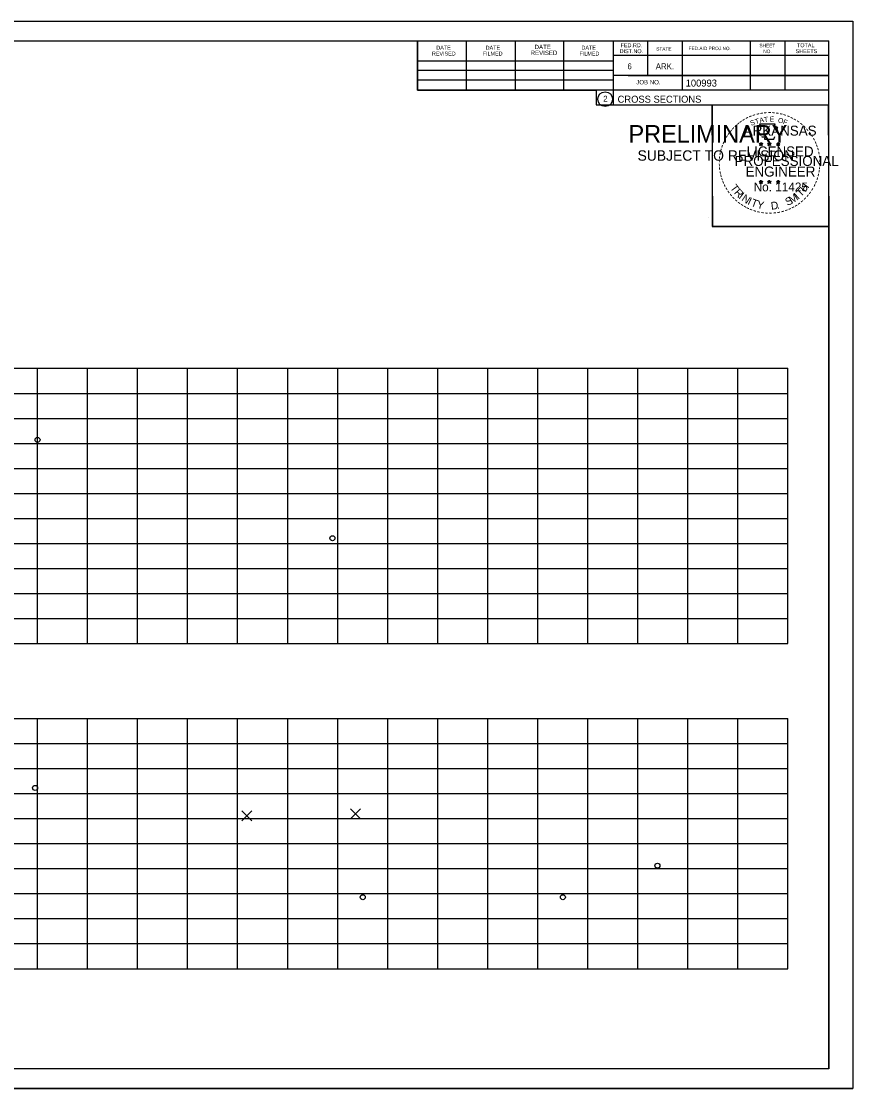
# Model space of a CAD drawing. Extents: x 4667 to 1632277, y -2100 to 724501.
# Drawn here: x 6136.3 to 6302.5, y -1323.8 to -1110.4 of the extents above; entities that cross this region are included whole.
import ezdxf

# ---------------------------------------------------------------- set-up
doc = ezdxf.new("R2010")
doc.units = 0
doc.layers.add('R_Grid', color=7, linetype='Continuous')
doc.layers.add('R_No Plot', color=7, linetype='Continuous')

msp = doc.modelspace()

# ---------------------------------------------------------------- linework, layer by layer
at = {"layer": 'R_Grid'}
for p, q in [((5989.52, -1179.77), (6289.52, -1179.77)), ((6139.52, -1234.77), (6139.52, -1179.77)), ((6149.52, -1234.77), (6149.52, -1179.77)), ((6159.52, -1234.77), (6159.52, -1179.77)), ((6169.52, -1234.77), (6169.52, -1179.77)), ((6179.52, -1234.77), (6179.52, -1179.77)), ((6189.52, -1234.77), (6189.52, -1179.77)), ((6199.52, -1234.77), (6199.52, -1179.77)), ((6209.52, -1234.77), (6209.52, -1179.77)), ((6219.52, -1234.77), (6219.52, -1179.77)), ((6229.52, -1234.77), (6229.52, -1179.77)), ((6239.52, -1234.77), (6239.52, -1179.77)), ((6249.52, -1234.77), (6249.52, -1179.77)), ((6259.52, -1234.77), (6259.52, -1179.77)), ((6269.52, -1234.77), (6269.52, -1179.77)), ((6279.52, -1234.77), (6279.52, -1179.77)), ((6289.52, -1234.77), (6289.52, -1179.77)), ((5989.52, -1184.77), (6289.52, -1184.77)), ((5989.52, -1189.77), (6289.52, -1189.77)), ((5989.52, -1194.77), (6289.52, -1194.77)), ((5989.52, -1199.77), (6289.52, -1199.77)), ((5989.52, -1204.77), (6289.52, -1204.77)), ((5989.52, -1209.77), (6289.52, -1209.77)), ((5989.52, -1214.77), (6289.52, -1214.77)), ((5989.52, -1219.77), (6289.52, -1219.77)), ((5989.52, -1224.77), (6289.52, -1224.77)), ((5989.52, -1229.77), (6289.52, -1229.77)), ((5989.52, -1234.77), (6289.52, -1234.77)), ((5989.52, -1249.77), (6289.52, -1249.77)), ((6139.52, -1299.77), (6139.52, -1249.77)), ((6149.52, -1299.77), (6149.52, -1249.77)), ((6159.52, -1299.77), (6159.52, -1249.77)), ((6169.52, -1299.77), (6169.52, -1249.77)), ((6179.52, -1299.77), (6179.52, -1249.77)), ((6189.52, -1299.77), (6189.52, -1249.77)), ((6199.52, -1299.77), (6199.52, -1249.77)), ((6209.52, -1299.77), (6209.52, -1249.77)), ((6219.52, -1299.77), (6219.52, -1249.77)), ((6229.52, -1299.77), (6229.52, -1249.77)), ((6239.52, -1299.77), (6239.52, -1249.77)), ((6249.52, -1299.77), (6249.52, -1249.77)), ((6259.52, -1299.77), (6259.52, -1249.77)), ((6269.52, -1299.77), (6269.52, -1249.77)), ((6279.52, -1299.77), (6279.52, -1249.77)), ((6289.52, -1299.77), (6289.52, -1249.77)), ((5989.52, -1254.77), (6289.52, -1254.77)), ((5989.52, -1259.77), (6289.52, -1259.77)), ((5989.52, -1264.77), (6289.52, -1264.77)), ((5989.52, -1269.77), (6289.52, -1269.77)), ((5989.52, -1274.77), (6289.52, -1274.77)), ((5989.52, -1279.77), (6289.52, -1279.77)), ((5989.52, -1284.77), (6289.52, -1284.77)), ((5989.52, -1289.77), (6289.52, -1289.77)), ((5989.52, -1294.77), (6289.52, -1294.77)), ((5989.52, -1299.77), (6289.52, -1299.77))]:
    msp.add_line(p, q, dxfattribs=at)
at = {"layer": 'R_No Plot'}
for p, q in [((5969.12, -1110.41), (6302.46, -1110.41)), ((5981.52, -1114.31), (6297.7, -1114.31)), ((6215.44, -1124.19), (6215.44, -1114.31)), ((6225.3, -1124.19), (6225.3, -1114.51)), ((6235.06, -1124.19), (6235.06, -1114.51)), ((6244.74, -1124.19), (6244.74, -1114.51)), ((6254.6, -1114.31), (6254.6, -1127.11)), ((6261.44, -1114.31), (6261.44, -1121.25)), ((6268.38, -1114.31), (6268.38, -1124.19)), ((6281.96, -1114.31), (6281.96, -1124.19)), ((6288.9, -1114.31), (6288.9, -1124.19)), ((6297.7, -1319.77), (6297.7, -1114.31)), ((6297.7, -1117.25), (6254.6, -1117.25)), ((6297.7, -1117.23), (6297.7, -1117.23)), ((6215.44, -1118.33), (6254.6, -1118.33)), ((6215.44, -1120.19), (6254.6, -1120.19)), ((6215.44, -1124.19), (6215.44, -1122.13)), ((6215.44, -1122.13), (6254.6, -1122.13)), ((6297.7, -1121.25), (6254.6, -1121.25)), ((6257.56, -1121.25), (6297.7, -1121.25)), ((6297.7, -1124.19), (6215.44, -1124.19)), ((6254.6, -1127.11), (6297.7, -1127.11)), ((6283.79, -1134.85), (6284.14, -1134.96)), ((6283.79, -1134.85), (6284.04, -1134.9)), ((6283.79, -1134.85), (6284.03, -1134.98)), ((6284.14, -1134.6), (6284.1, -1134.85)), ((6284.14, -1134.96), (6284.14, -1134.6)), ((6284.14, -1134.6), (6284.19, -1134.85)), ((6284.49, -1134.85), (6284.14, -1134.96)), ((6284.49, -1134.85), (6284.2, -1134.9)), ((6284.49, -1134.85), (6284.28, -1134.96)), ((6285.46, -1134.85), (6285.81, -1134.96)), ((6285.46, -1134.85), (6285.71, -1134.9)), ((6285.46, -1134.85), (6285.7, -1134.98)), ((6285.81, -1134.6), (6285.77, -1134.85)), ((6285.81, -1134.96), (6285.81, -1134.6)), ((6285.81, -1134.6), (6285.86, -1134.85)), ((6286.16, -1134.85), (6285.81, -1134.96)), ((6286.16, -1134.85), (6285.87, -1134.9)), ((6286.16, -1134.85), (6285.95, -1134.96)), ((6287.22, -1134.87), (6287.57, -1134.98)), ((6287.22, -1134.87), (6287.48, -1134.91)), ((6287.22, -1134.87), (6287.46, -1134.99)), ((6287.57, -1134.61), (6287.53, -1134.86)), ((6287.57, -1134.98), (6287.57, -1134.61)), ((6287.57, -1134.61), (6287.62, -1134.86)), ((6287.92, -1134.87), (6287.57, -1134.98)), ((6287.92, -1134.87), (6287.63, -1134.91)), ((6287.92, -1134.87), (6287.72, -1134.97)), ((6283.92, -1135.26), (6284.14, -1134.96)), ((6283.92, -1135.26), (6284.05, -1135.02)), ((6283.92, -1135.26), (6284.14, -1135.04)), ((6284.35, -1135.26), (6284.14, -1134.96)), ((6284.35, -1135.26), (6284.14, -1135.05)), ((6284.35, -1135.26), (6284.21, -1134.97)), ((6285.59, -1135.26), (6285.81, -1134.96)), ((6285.59, -1135.26), (6285.72, -1135.02)), ((6285.59, -1135.26), (6285.81, -1135.04)), ((6286.02, -1135.26), (6285.81, -1134.96)), ((6286.02, -1135.26), (6285.81, -1135.05)), ((6286.02, -1135.26), (6285.88, -1134.97)), ((6287.36, -1135.27), (6287.57, -1134.98)), ((6287.36, -1135.27), (6287.48, -1135.03)), ((6287.36, -1135.27), (6287.57, -1135.06)), ((6287.79, -1135.27), (6287.57, -1134.98)), ((6287.79, -1135.27), (6287.57, -1135.06)), ((6287.79, -1135.27), (6287.65, -1134.98)), ((6283.79, -1142.43), (6284.13, -1142.54)), ((6283.79, -1142.43), (6284.04, -1142.47)), ((6283.79, -1142.43), (6284.02, -1142.55)), ((6283.92, -1142.83), (6284.13, -1142.54)), ((6283.92, -1142.83), (6284.04, -1142.59)), ((6283.92, -1142.83), (6284.13, -1142.62)), ((6284.13, -1142.17), (6284.09, -1142.42)), ((6284.13, -1142.54), (6284.13, -1142.17)), ((6284.13, -1142.17), (6284.18, -1142.42)), ((6284.48, -1142.43), (6284.13, -1142.54)), ((6284.35, -1142.83), (6284.13, -1142.54)), ((6284.35, -1142.83), (6284.13, -1142.62)), ((6284.48, -1142.43), (6284.2, -1142.48)), ((6284.35, -1142.83), (6284.21, -1142.54)), ((6284.48, -1142.43), (6284.28, -1142.53)), ((6285.45, -1142.43), (6285.8, -1142.54)), ((6285.45, -1142.43), (6285.71, -1142.47)), ((6285.45, -1142.43), (6285.69, -1142.55)), ((6285.59, -1142.83), (6285.8, -1142.54)), ((6285.59, -1142.83), (6285.71, -1142.59)), ((6285.59, -1142.83), (6285.8, -1142.62)), ((6285.8, -1142.17), (6285.76, -1142.42)), ((6285.8, -1142.54), (6285.8, -1142.17)), ((6285.8, -1142.17), (6285.85, -1142.42)), ((6286.15, -1142.43), (6285.8, -1142.54)), ((6286.02, -1142.83), (6285.8, -1142.54)), ((6286.02, -1142.83), (6285.8, -1142.62)), ((6286.15, -1142.43), (6285.86, -1142.48)), ((6286.02, -1142.83), (6285.88, -1142.54)), ((6286.15, -1142.43), (6285.95, -1142.53)), ((6287.22, -1142.44), (6287.57, -1142.55)), ((6287.22, -1142.44), (6287.47, -1142.48)), ((6287.22, -1142.44), (6287.46, -1142.56)), ((6287.35, -1142.84), (6287.57, -1142.55)), ((6287.35, -1142.84), (6287.48, -1142.6)), ((6287.35, -1142.84), (6287.57, -1142.63)), ((6287.57, -1142.18), (6287.53, -1142.43)), ((6287.57, -1142.55), (6287.57, -1142.18)), ((6287.57, -1142.18), (6287.62, -1142.43)), ((6287.92, -1142.44), (6287.57, -1142.55)), ((6287.78, -1142.84), (6287.57, -1142.55)), ((6287.78, -1142.84), (6287.57, -1142.63)), ((6287.92, -1142.44), (6287.63, -1142.49)), ((6287.78, -1142.84), (6287.65, -1142.55)), ((6287.92, -1142.44), (6287.71, -1142.54)), ((6273.74, -1149.56), (6273.74, -1149.56)), ((6297.7, -1319.77), (5981.52, -1319.77)), ((5969.12, -1323.75), (6302.46, -1323.75))]:
    msp.add_line(p, q, dxfattribs=at)
for points in [[(5969.12, -1110.41), (6302.46, -1110.41), (6302.46, -1323.75), (5969.12, -1323.75)], [(6215.44, -1114.31), (6215.44, -1124.19), (6251.18, -1124.19), (6251.18, -1127.11), (6274.38, -1127.11), (6274.38, -1151.44), (6297.7, -1151.44), (6297.7, -1319.77), (5981.52, -1319.77), (5981.52, -1114.31)], [(6274.38, -1127.11), (6297.58, -1127.11), (6297.7, -1151.44), (6274.5, -1151.44)]]:
    msp.add_lwpolyline(points, close=True, dxfattribs=at)
for points in [[(6283.83, -1130.98), (6284.1, -1131.8)], [(6287.34, -1131.9), (6287.48, -1131.61), (6286.8, -1131.64), (6286.95, -1130.98), (6283.83, -1130.98)], [(6284.14, -1134.6), (6284.35, -1135.26), (6283.79, -1134.85), (6284.49, -1134.85), (6283.92, -1135.26), (6284.14, -1134.6)], [(6284.32, -1133.4), (6284.32, -1133.49), (6284.89, -1133.5), (6284.83, -1133.98), (6286.7, -1133.98), (6286.9, -1133.44)], [(6285.81, -1134.6), (6286.02, -1135.26), (6285.46, -1134.85), (6286.16, -1134.85), (6285.59, -1135.26), (6285.81, -1134.6)], [(6287.57, -1134.61), (6287.79, -1135.27), (6287.22, -1134.87), (6287.92, -1134.87), (6287.36, -1135.27), (6287.57, -1134.61)], [(6284.13, -1142.17), (6284.35, -1142.83), (6283.79, -1142.43), (6284.48, -1142.43), (6283.92, -1142.83), (6284.13, -1142.17)], [(6285.8, -1142.17), (6286.02, -1142.83), (6285.45, -1142.43), (6286.15, -1142.43), (6285.59, -1142.83), (6285.8, -1142.17)], [(6287.57, -1142.18), (6287.78, -1142.84), (6287.22, -1142.44), (6287.92, -1142.44), (6287.35, -1142.84), (6287.57, -1142.18)], [(6181.35, -1269.23), (6180.35, -1268.23), (6181.35, -1269.23), (6180.35, -1270.23), (6181.35, -1269.23), (6182.35, -1270.23), (6181.35, -1269.23), (6182.35, -1268.23)], [(6203.06, -1268.83), (6202.06, -1267.83), (6203.06, -1268.83), (6202.06, -1269.83), (6203.06, -1268.83), (6204.06, -1269.83), (6203.06, -1268.83), (6204.06, -1267.83)]]:
    msp.add_lwpolyline(points, dxfattribs=at)
for centre, radius in [((6252.99, -1125.97), 1.47), ((6284.14, -1134.97), 0.172), ((6284.14, -1134.97), 0.145), ((6284.14, -1134.97), 0.116), ((6284.14, -1134.97), 0.0991), ((6284.14, -1134.97), 0.0747), ((6284.14, -1134.97), 0.0495), ((6284.14, -1134.97), 0.0296), ((6285.81, -1134.97), 0.172), ((6285.81, -1134.97), 0.145), ((6285.81, -1134.97), 0.116), ((6285.81, -1134.97), 0.0991), ((6285.81, -1134.97), 0.0747), ((6285.81, -1134.97), 0.0495), ((6285.81, -1134.97), 0.0296), ((6287.57, -1134.98), 0.172), ((6287.57, -1134.98), 0.145), ((6287.57, -1134.98), 0.116), ((6287.57, -1134.98), 0.0991), ((6287.57, -1134.98), 0.0747), ((6287.57, -1134.98), 0.0495), ((6287.57, -1134.98), 0.0296), ((6284.13, -1142.54), 0.172), ((6284.13, -1142.54), 0.145), ((6284.13, -1142.54), 0.116), ((6284.13, -1142.54), 0.0991), ((6284.13, -1142.54), 0.0747), ((6284.13, -1142.54), 0.0495), ((6284.13, -1142.54), 0.0296), ((6285.8, -1142.54), 0.172), ((6285.8, -1142.54), 0.145), ((6285.8, -1142.54), 0.116), ((6285.8, -1142.54), 0.0991), ((6285.8, -1142.54), 0.0747), ((6285.8, -1142.54), 0.0495), ((6285.8, -1142.54), 0.0296), ((6287.57, -1142.55), 0.172), ((6287.57, -1142.55), 0.145), ((6287.57, -1142.55), 0.116), ((6287.57, -1142.55), 0.0991), ((6287.57, -1142.55), 0.0747), ((6287.57, -1142.55), 0.0495), ((6287.57, -1142.55), 0.0296), ((6139.52, -1194.07), 0.5), ((6198.46, -1213.72), 0.5), ((6198.46, -1213.72), 0.5), ((6139.02, -1263.64), 0.5), ((6139.02, -1263.64), 0.5), ((6263.43, -1279.18), 0.5), ((6204.53, -1285.48), 0.5), ((6244.53, -1285.48), 0.5)]:
    msp.add_circle(centre, radius, dxfattribs=at)

# ---------------------------------------------------------------- texts
for s, height, rotation, p in [('DATE', 0.782, 360, (6219.24, -1116.07)), ('DATE', 0.782, 360, (6229.1, -1116.07)), ('DATE', 0.879, 360, (6238.88, -1115.97)), ('DATE', 0.782, 360, (6248.26, -1116.07)), ('FED.RD.', 0.782, 360, (6256.08, -1115.59)), ('STATE', 0.684, 360, (6263.2, -1116.27)), ('FED.AID PROJ.NO.', 0.684, 360, (6269.66, -1116.17)), ('SHEET', 0.684, 360, (6283.82, -1115.59)), ('TOTAL', 0.782, 360, (6291.34, -1115.59)), ('REVISED', 0.782, 360, (6218.36, -1117.25)), ('FILMED', 0.782, 360, (6228.52, -1117.25)), ('REVISED', 0.879, 360, (6238.1, -1117.15)), ('FILMED', 0.782, 360, (6247.86, -1117.25)), ('DIST.NO.', 0.782, 360, (6255.88, -1116.77)), ('NO.', 0.684, 360, (6284.6, -1116.77)), ('SHEETS', 0.782, 360, (6291.06, -1116.77)), ('6', 1.17, 360, (6257.44, -1119.99)), ('ARK.', 1.172, 360, (6263.1, -1119.99)), ('JOB NO.', 0.879, 360, (6259.2, -1123.01)), ('100993', 1.4, 360, (6269.08, -1123.45)), ('2', 1.17, 360, (6252.61, -1126.46)), ('CROSS SECTIONS', 1.4, 360, (6255.47, -1126.68)), ('-', 1.6, 0.1862, (6285.51, -1129.26)), ('-', 1.6, 38.9507, (6279.66, -1131.58)), ('-', 1.6, 36.2317, (6280.14, -1131.2)), ('-', 1.6, 34.0636, (6280.71, -1130.8)), ('-', 1.6, 28.7918, (6281.31, -1130.43)), ('-', 1.6, 24.3072, (6281.94, -1130.12)), ('S', 1, 21.594, (6282.18, -1131.3)), ('-', 1.6, 19.1761, (6282.58, -1129.85)), ('T', 1, 16.4036, (6283.1, -1130.97)), ('-', 1.6, 13.6301, (6283.33, -1129.61)), ('A', 1, 11.2132, (6283.92, -1130.72)), ('-', 1.6, 10.2193, (6284.01, -1129.45)), ('T', 1, 6.0228, (6284.77, -1130.55)), ('-', 1.6, 5.8968, (6284.73, -1129.34)), ('E', 1, 0.8323, (6285.88, -1130.44)), ('-', 1.6, 357.743, (6286.23, -1129.28)), ('-', 1.6, 352.1617, (6286.97, -1129.33)), ('O', 1, 350.4515, (6287.48, -1130.65)), ('-', 1.6, 347.2049, (6287.69, -1129.45)), ('F', 1, 340.0707, (6288.44, -1130.88)), ('-', 1.6, 342.3362, (6288.33, -1129.6)), ('-', 1.6, 337.8551, (6289.06, -1129.82)), ('-', 1.6, 334.1211, (6289.69, -1130.1)), ('-', 1.6, 329.6409, (6290.27, -1130.38)), ('-', 1.6, 325.8627, (6290.92, -1130.74)), ('-', 1.6, 320.5297, (6291.53, -1131.17)), ('PRELIMINARY', 3.5, 360, (6257.66, -1134.65)), ('DWB', 0.01, 360, (6258.4, -1132.8)), ('-', 1.6, 54.2325, (6277.96, -1133.53)), ('-', 1.6, 50.6142, (6278.38, -1132.96)), ('-', 1.6, 48.423, (6278.78, -1132.47)), ('-', 1.6, 42.9622, (6279.23, -1131.99)), ('ARKANSAS', 2, 360, (6280.68, -1133.26)), ('-', 1.6, 315.5786, (6292.12, -1131.65)), ('-', 1.6, 309.8797, (6292.69, -1132.2)), ('-', 1.6, 306.6522, (6293.22, -1132.81)), ('-', 1.6, 67.7743, (6277.07, -1135.28)), ('-', 1.6, 62.8713, (6277.32, -1134.67)), ('-', 1.6, 58.0706, (6277.64, -1134.05)), ('-', 1.4, 303.6753, (6293.7, -1133.37)), ('-', 1.6, 299.6684, (6294.02, -1133.98)), ('-', 1.6, 294.6628, (6294.35, -1134.59)), ('SUBJECT TO REVISION', 2.0751, 360, (6259.46, -1138.27)), ('-', 1.6, 81.2013, (6276.52, -1137.33)), ('-', 1.6, 75.461, (6276.65, -1136.62)), ('-', 1.6, 72.3945, (6276.85, -1135.91)), ('LICENSED', 2, 360, (6281.28, -1137.41)), ('DWB', 0.01, 360, (6284.13, -1134.97)), ('DWB', 0.01, 360, (6285.8, -1134.97)), ('DWB', 0.01, 360, (6287.56, -1134.98)), ('-', 1.6, 290.5728, (6294.6, -1135.17)), ('-', 1.6, 285.1233, (6294.84, -1135.75)), ('-', 1.6, 280.5493, (6295.04, -1136.49)), ('-', 1.6, 94.1959, (6276.45, -1139.45)), ('-', 1.6, 89.0622, (6276.42, -1138.73)), ('-', 1.6, 85.1863, (6276.44, -1138.03)), ('PROFESSIONAL', 2, 360, (6278.86, -1139.32)), ('-', 1.6, 276.5962, (6295.2, -1137.26)), ('-', 1.6, 274.3301, (6295.26, -1137.98)), ('-', 1.6, 269.9407, (6295.29, -1138.61)), ('-', 1.6, 98.9479, (6276.52, -1140.12)), ('-', 1.6, 101.7149, (6276.66, -1140.85)), ('-', 1.6, 105.4578, (6276.82, -1141.45)), ('ENGINEER', 2, 360, (6281.04, -1141.44)), ('-', 1.6, 255.7626, (6295.09, -1140.61)), ('-', 1.6, 260.9953, (6295.2, -1139.93)), ('-', 1.6, 263.5172, (6295.28, -1139.28)), ('-', 1.6, 109.0874, (6277.04, -1142.08)), ('-', 1.6, 114.0643, (6277.29, -1142.67)), ('-', 1.6, 115.7289, (6277.59, -1143.29)), ('T', 1.54, 306.0406, (6277.89, -1143.7)), ('No. 11425', 1.757, 360, (6282.67, -1144.39)), ('DWB', 0.01, 360, (6284.12, -1142.54)), ('DWB', 0.01, 360, (6285.79, -1142.54)), ('DWB', 0.01, 360, (6287.56, -1142.55)), ('H', 1.54, 54.6088, (6293.01, -1144.66)), ('-', 1.6, 244.6197, (6294.43, -1142.63)), ('-', 1.6, 247.8887, (6294.69, -1142)), ('-', 1.6, 252.8681, (6294.91, -1141.33)), ('-', 1.6, 120.4471, (6277.95, -1143.88)), ('-', 1.6, 125.8934, (6278.35, -1144.44)), ('-', 1.6, 130.7181, (6278.82, -1144.99)), ('-', 1.6, 134.2238, (6279.33, -1145.54)), ('R', 1.54, 314.005, (6278.66, -1144.75)), ('I', 1.54, 321.9694, (6279.56, -1145.68)), ('N', 1.54, 326.5002, (6280.12, -1146.15)), ('I', 1.54, 335.3603, (6281.33, -1146.94)), ('S', 1.54, 26.9312, (6289.44, -1147.34)), ('M', 1.54, 32.6563, (6290.28, -1146.93)), ('I', 1.54, 42.1136, (6291.56, -1146.08)), ('T', 1.54, 46.6444, (6292.12, -1145.61)), ('-', 1.6, 225.7653, (6292.72, -1145.17)), ('-', 1.6, 231.2538, (6293.2, -1144.6)), ('-', 1.6, 233.8452, (6293.63, -1144.04)), ('-', 1.6, 239.0712, (6294.03, -1143.39)), ('-', 1.6, 138.9338, (6279.86, -1146)), ('-', 1.6, 144.6463, (6280.41, -1146.41)), ('-', 1.6, 148.0898, (6280.98, -1146.78)), ('-', 1.6, 151.5704, (6281.55, -1147.1)), ('-', 1.6, 154.6002, (6282.08, -1147.35)), ('T', 1.54, 339.8912, (6281.99, -1147.26)), ('Y', 1.54, 347.8556, (6283.21, -1147.71)), ('D', 1.54, 6.3969, (6286.19, -1148.07)), ('.', 1.54, 13.7642, (6287.39, -1147.94)), ('-', 1.6, 204.2516, (6289.94, -1147.2)), ('-', 1.6, 207.3568, (6290.56, -1146.88)), ('-', 1.6, 212.2491, (6291.12, -1146.54)), ('-', 1.6, 215.7363, (6291.65, -1146.15)), ('-', 1.6, 221.0851, (6292.2, -1145.68)), ('-', 1.6, 158.5612, (6282.7, -1147.6)), ('-', 1.6, 162.7983, (6283.39, -1147.82)), ('-', 1.6, 167.5555, (6284.1, -1147.98)), ('-', 1.6, 173.1155, (6284.87, -1148.09)), ('-', 1.6, 176.5183, (6285.62, -1148.14)), ('-', 1.6, 181.5918, (6286.37, -1148.12)), ('-', 1.6, 185.8167, (6287.18, -1148.05)), ('-', 1.6, 191.2858, (6287.91, -1147.92)), ('-', 1.6, 195.4743, (6288.64, -1147.72)), ('-', 1.6, 200.7184, (6289.32, -1147.47))]:
    msp.add_text(s, height=height, rotation=rotation, dxfattribs=at).set_placement(p)

doc.saveas('drawing.dxf')
